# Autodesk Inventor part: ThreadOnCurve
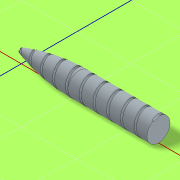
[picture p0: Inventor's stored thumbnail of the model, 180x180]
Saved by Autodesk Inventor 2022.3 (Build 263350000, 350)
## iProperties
Created: 2023-07
Part Number: ThreadOnCurve
Material: Generic
Document SubType Name: Modeling
Designer: irinventor.com
Density: 1 g/cm^3
Appearance: Default(2)
Author: irinventor.com
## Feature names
1. Revolution1
2. Sweep1
## Parameters: d1 = 90 deg, d3 = 4.2 mm, d14 = 0, d15 = 0, d16 = 0, d18 = 0.8 mm, d19 = 0, d20 = 0
